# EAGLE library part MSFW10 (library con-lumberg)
MSF CONNECTOR
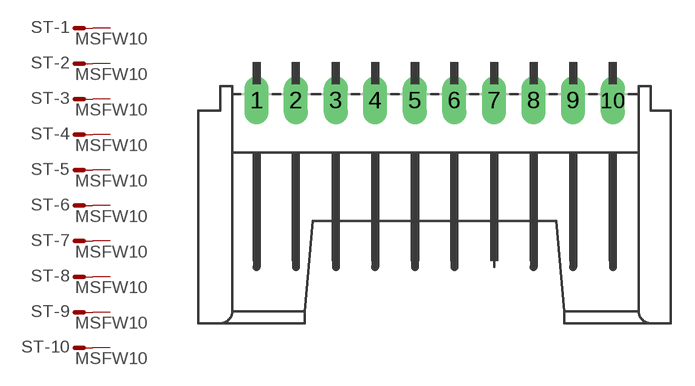
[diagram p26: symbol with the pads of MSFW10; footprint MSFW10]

Designator prefix ST; gates -1=M -2=M -3=M -4=M -5=M -6=M -7=M -8=M -9=M -10=M

## MSFW10 (OC_FARNELL: unknown; OC_NEWARK: unknown)  [MSFW10]
1  -1:S  pas
2  -2:S  pas
3  -3:S  pas
4  -4:S  pas
5  -5:S  pas
6  -6:S  pas
7  -7:S  pas
8  -8:S  pas
9  -9:S  pas
10  -10:S  pas

## Footprint MSFW10 (pad centres in mm)
MSF CONNECTOR Buerklin Nr. 56 F 583
drill 1.016 long: 1 0,1.905; 2 2.489,1.905; 3 5.004,1.905; 4 7.493,1.905; 5 10.008,1.905; 6 12.497,1.905; 7 15.011,1.905; 8 17.501,1.905; 9 19.99,1.905; 10 22.504,1.905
